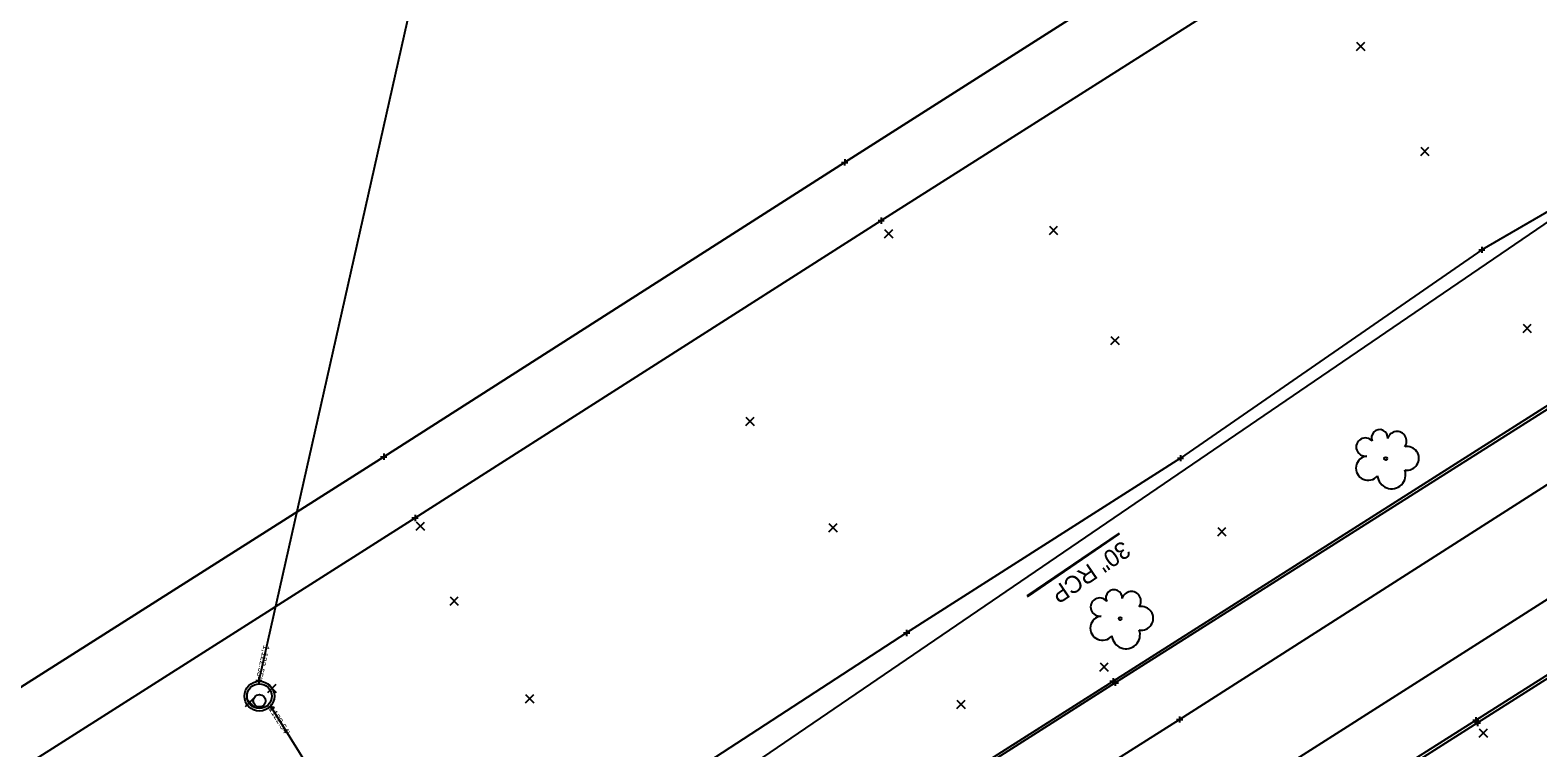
# Model space of a CAD drawing. Extents: x 142461 to 147261, y 511126 to 514697.
# Drawn here: x 144940.1 to 145184.1, y 513109.1 to 513225.2 of the extents above; entities that cross this region are included whole.
import ezdxf

# ---------------------------------------------------------------- set-up
doc = ezdxf.new("R2010")
doc.units = 0
for name, color, linetype in [('DR_X_Cells', 7, 'Continuous'), ('DR_X_Elev_Flow', 7, 'Continuous'), ('DR_X_Storm_Sewer', 7, 'Continuous'), ('DR_X_Text', 7, 'Continuous'), ('GK_Drainage_Nodes', 7, 'Continuous'), ('PM_X_Surveyed_Line', 7, 'Continuous'), ('PV_X_Curb', 7, 'Continuous'), ('PV_X_EOP', 7, 'Continuous'), ('SC_Scratch1', 7, 'Continuous'), ('SV_X_Original_Ground', 7, 'Continuous'), ('SV_X_Random_Point', 7, 'Continuous'), ('SV_X_Shot_Marker', 7, 'Continuous'), ('SV_X_Toe_of_Slope', 7, 'Continuous'), ('UT_X_Sanitary_Line', 7, 'Continuous'), ('VG_X_Cells', 7, 'Continuous')]:
    doc.layers.add(name, color=color, linetype=linetype)

msp = doc.modelspace()

# ---------------------------------------------------------------- linework, layer by layer
at = {"layer": 'DR_X_Cells'}
for centre, radius in [((144977.22, 513117.44), 2.42), ((144977.22, 513117.44), 2), ((144977.22, 513116.69), 1)]:
    msp.add_circle(centre, radius, dxfattribs=at)
at = {"layer": 'DR_X_Elev_Flow'}
for p, q in [((144977.14, 513120.5), (144977.14, 513119.5)), ((144976.64, 513120), (144977.64, 513120)), ((144977.14, 513120), (144977.14, 513120)), ((144978.61, 513115.64), (144979.61, 513115.64)), ((144979.11, 513116.14), (144979.11, 513115.14)), ((144979.11, 513115.64), (144979.11, 513115.64))]:
    msp.add_line(p, q, dxfattribs=at)
at = {"layer": 'DR_X_Storm_Sewer'}
msp.add_line((145313.55, 513281.39), (144904.71, 513002.46), dxfattribs=at)
at = {"layer": 'DR_X_Text'}
for p, q in [((145101.5, 513133.65), (145116.41, 513143.82)), ((145101.52, 513133.52), (145116.43, 513143.7))]:
    msp.add_line(p, q, dxfattribs=at)
at = {"layer": 'GK_Drainage_Nodes'}
for p, q in [((144977.22, 513119.44), (144977.22, 513119.44)), ((144977.22, 513117.44), (144977.22, 513117.44)), ((144977.22, 513117.44), (144977.22, 513117.44)), ((144977.22, 513116.69), (144977.22, 513116.69)), ((144977.22, 513115.44), (144977.22, 513115.44))]:
    msp.add_line(p, q, dxfattribs=at)
msp.add_circle((144977.22, 513117.44), 2, dxfattribs=at)
at = {"layer": 'PM_X_Surveyed_Line'}
for points in [[(144079.63, 512572.09), (144161.19, 512623.62), (144232.68, 512669.39), (144303.71, 512715.03), (144372.67, 512758.92), (144417.33, 512787.4), (144522.55, 512854.42), (144628.96, 512922.1), (144693.88, 512963.42), (144795.96, 513028.33), (144851.81, 513063.86), (144912.86, 513102.61), (144997.35, 513156.18), (145071.95, 513203.81), (145158.73, 513259.05)], [(144161.19, 512623.62), (144234.91, 512664.76), (144308.58, 512704.75), (144382.31, 512742.08), (144431.43, 512764.26), (144460.46, 512777.08), (144499.91, 512794.34), (144547.7, 512814.68), (144592.59, 512833.3), (144667.23, 512864.35), (144709.98, 512882.09), (144731.76, 512891.11), (144777.76, 512910.35), (144847.49, 512940.98), (144877.97, 512956.57), (144906.17, 512973.31), (144970.66, 513014.86), (145008.54, 513039.23), (145047.45, 513063.87), (145126.17, 513113.66), (145208.14, 513166.05), (145269.39, 513204.92)], [(144979.87, 513002.18), (145015.44, 513024.96), (145056.46, 513050.99), (145134.2, 513100.33), (145217.05, 513153.1), (145277.89, 513191.73), (145294.07, 513201.96)]]:
    msp.add_lwpolyline(points, dxfattribs=at)
at = {"layer": 'PV_X_Curb'}
for p, q in [((145217.64, 513140.59), (145174.39, 513113.11)), ((145174.39, 513113.11), (145138.38, 513090.38))]:
    msp.add_line(p, q, dxfattribs=at)
msp.add_lwpolyline([(144906.62, 512975.04), (144910.56, 512977.96), (144915.88, 512983.2), (144920.32, 512988.51), (144935.68, 513005.16), (144948.67, 513014.13), (144965.59, 513024.78), (145041.73, 513073.1), (145115.39, 513119.87), (145203.02, 513175.49), (145259.95, 513211.93), (145276.5, 513223.26), (145307.25, 513248.71)], dxfattribs=at)
at = {"layer": 'PV_X_EOP'}
for p, q in [((145174.12, 513113.56), (145217.4, 513141.09)), ((145138.07, 513090.84), (145174.12, 513113.56))]:
    msp.add_line(p, q, dxfattribs=at)
for points in [[(144423.14, 512777.38), (144529.59, 512845.63), (144635.07, 512912.79), (144699.77, 512953.97), (144801.25, 513018.67), (144857.84, 513054.39), (144918.27, 513092.86), (145002.41, 513146.27), (145077.85, 513194.39), (145164.32, 513249.25)], [(145308.5, 513249.32), (145276.87, 513222.85), (145260.3, 513211.35), (145203.28, 513174.99), (145115.75, 513119.59), (145041.93, 513072.6), (144965.91, 513024.3), (144949.02, 513013.46), (144936.1, 513004.72), (144920.88, 512988.16), (144917.39, 512983.57), (144918.93, 512982.03), (144917.24, 512980.52), (144915.69, 512981.95)]]:
    msp.add_lwpolyline(points, dxfattribs=at)
at = {"layer": 'SV_X_Original_Ground'}
msp.add_lwpolyline([(145158.73, 513259.05), (145071.95, 513203.81), (144997.35, 513156.18), (144912.86, 513102.61), (144851.81, 513063.86), (144795.96, 513028.33), (144693.88, 512963.42), (144628.96, 512922.1), (144522.55, 512854.42), (144417.33, 512787.4), (144372.67, 512758.92), (144303.71, 512715.03), (144232.68, 512669.39), (144161.19, 512623.62), (144079.63, 512572.09)], dxfattribs=at)
at = {"layer": 'SV_X_Random_Point'}
for p, q in [((145154.8, 513221.91), (145156.13, 513223.25)), ((145154.8, 513223.25), (145156.13, 513221.91)), ((145165.18, 513204.91), (145166.51, 513206.25)), ((145165.18, 513206.25), (145166.51, 513204.91)), ((145078.41, 513191.6), (145079.76, 513192.93)), ((145078.42, 513192.94), (145079.74, 513191.59)), ((145105.09, 513192.14), (145106.42, 513193.48)), ((145105.09, 513193.48), (145106.42, 513192.14)), ((145181.75, 513176.3), (145183.08, 513177.64)), ((145181.75, 513177.64), (145183.08, 513176.3)), ((145115.03, 513174.33), (145116.37, 513175.66)), ((145115.03, 513175.66), (145116.37, 513174.33)), ((145055.95, 513161.23), (145057.29, 513162.56)), ((145055.95, 513162.56), (145057.29, 513161.23)), ((145002.59, 513144.3), (145003.94, 513145.62)), ((145002.61, 513145.63), (145003.93, 513144.29)), ((145069.41, 513144.02), (145070.74, 513145.36)), ((145069.41, 513145.36), (145070.74, 513144.02)), ((145132.34, 513143.38), (145133.67, 513144.72)), ((145132.34, 513144.72), (145133.67, 513143.38)), ((145008.08, 513132.15), (145009.42, 513133.49)), ((145008.08, 513133.49), (145009.42, 513132.15)), ((145113.27, 513121.51), (145114.62, 513122.83)), ((145113.28, 513122.85), (145114.6, 513121.5)), ((144978.57, 513118.04), (144979.92, 513119.36)), ((144978.59, 513119.38), (144979.91, 513118.03)), ((144974.99, 513115.77), (144976.34, 513117.09)), ((144975.01, 513117.11), (144976.33, 513115.76)), ((145020.31, 513116.37), (145021.64, 513117.7)), ((145020.31, 513117.7), (145021.64, 513116.37)), ((145090.11, 513115.43), (145091.44, 513116.77)), ((145090.11, 513116.77), (145091.44, 513115.43)), ((145174.65, 513110.81), (145176, 513112.13)), ((145174.67, 513112.15), (145175.99, 513110.8))]:
    msp.add_line(p, q, dxfattribs=at)
at = {"layer": 'SV_X_Shot_Marker'}
for p, q in [((145071.45, 513203.81), (145072.45, 513203.8)), ((145071.96, 513204.31), (145071.95, 513203.31)), ((145071.95, 513203.81), (145071.95, 513203.81)), ((145077.35, 513194.39), (145078.35, 513194.38)), ((145077.85, 513194.89), (145077.84, 513193.89)), ((145077.85, 513194.39), (145077.85, 513194.39)), ((145174.58, 513189.66), (145175.58, 513189.66)), ((145175.08, 513190.16), (145175.08, 513189.16)), ((145175.08, 513189.66), (145175.08, 513189.66)), ((144996.85, 513156.19), (144997.85, 513156.18)), ((144997.36, 513156.68), (144997.34, 513155.68)), ((144997.35, 513156.18), (144997.35, 513156.18)), ((145125.81, 513155.94), (145126.81, 513155.94)), ((145126.31, 513156.44), (145126.31, 513155.44)), ((145126.31, 513155.94), (145126.31, 513155.94)), ((145001.91, 513146.28), (145002.91, 513146.27)), ((145002.42, 513146.77), (145002.41, 513145.77)), ((145002.41, 513146.27), (145002.41, 513146.27)), ((145081.98, 513128.17), (145081.98, 513127.17)), ((145081.48, 513127.67), (145082.48, 513127.67)), ((145081.98, 513127.67), (145081.98, 513127.67)), ((145114.89, 513119.88), (145115.89, 513119.87)), ((145115.25, 513119.59), (145116.25, 513119.58)), ((145115.39, 513120.37), (145115.38, 513119.37)), ((145115.39, 513119.87), (145115.39, 513119.87)), ((145115.75, 513120.09), (145115.74, 513119.09)), ((145115.75, 513119.59), (145115.75, 513119.59)), ((145125.67, 513113.66), (145126.67, 513113.65)), ((145126.17, 513114.16), (145126.16, 513113.16)), ((145126.17, 513113.66), (145126.17, 513113.66)), ((145173.62, 513113.57), (145174.62, 513113.56)), ((145174.13, 513114.06), (145174.12, 513113.06)), ((145174.12, 513113.56), (145174.12, 513113.56)), ((145174.39, 513113.61), (145174.38, 513112.61)), ((145173.89, 513113.11), (145174.89, 513113.1)), ((145174.39, 513113.11), (145174.39, 513113.11))]:
    msp.add_line(p, q, dxfattribs=at)
at = {"layer": 'SV_X_Toe_of_Slope'}
msp.add_lwpolyline([(145536.33, 513468.51), (145487.34, 513431.87), (145445.96, 513398.71), (145400.54, 513359.53), (145354.59, 513321.64), (145305.79, 513280.24), (145266.24, 513246.77), (145228.58, 513220.65), (145175.08, 513189.66), (145126.31, 513155.94), (145081.98, 513127.67), (145034.97, 513097.1), (144983.36, 513063.49), (144934.41, 513028.84), (144889.77, 512994.77), (144833.63, 512962.42), (144772.97, 512934.59), (144716.73, 512910.04), (144663.56, 512886.77), (144614.86, 512866.63), (144547.92, 512838.93)], dxfattribs=at)
at = {"layer": 'UT_X_Sanitary_Line'}
for p, q in [((145049.95, 513443.91), (144977.14, 513120)), ((144979.11, 513115.64), (145082.93, 512950.11))]:
    msp.add_line(p, q, dxfattribs=at)
at = {"layer": 'VG_X_Cells'}
for centre in [(145159.52, 513155.89), (145116.53, 513130)]:
    msp.add_circle(centre, 0.24, dxfattribs=at)
for centre, radius, start, end in [((145158.54, 513159.26), 1.32, 354.0047, 205.9741), ((145161.35, 513158.72), 1.55, 323.83, 165.0376), ((145156.21, 513157.75), 1.47, 39.0625, 279.5412), ((145162.98, 513155.93), 1.91, 259.1453, 101.4596), ((145156.67, 513154.34), 1.97, 96.1722, 320.5737), ((145160.47, 513153.28), 2.28, 184.9476, 19.4572), ((145113.22, 513131.86), 1.47, 39.0625, 279.5412), ((145115.55, 513133.36), 1.32, 354.0047, 205.9741), ((145118.36, 513132.83), 1.55, 323.83, 165.0376), ((145113.68, 513128.45), 1.97, 96.1722, 320.5737), ((145119.99, 513130.03), 1.91, 259.1453, 101.4596), ((145117.48, 513127.39), 2.28, 184.9476, 19.4572)]:
    msp.add_arc(centre, radius, start, end, dxfattribs=at)

# ---------------------------------------------------------------- texts
at = {"layer": 'DR_X_Text'}
msp.add_text('30" RCP', height=2.8, rotation=214.3038, dxfattribs=at).set_placement((145116.96, 513142.72))
at = {"layer": 'SC_Scratch1'}
for s, rotation, p in [("1,122.55'", 257.333, (144977.92, 513125.75)), ("1122.54'", 302.0959, (144978.69, 513115.38))]:
    msp.add_text(s, height=1, rotation=rotation, dxfattribs=at).set_placement(p)

doc.saveas('drawing.dxf')
